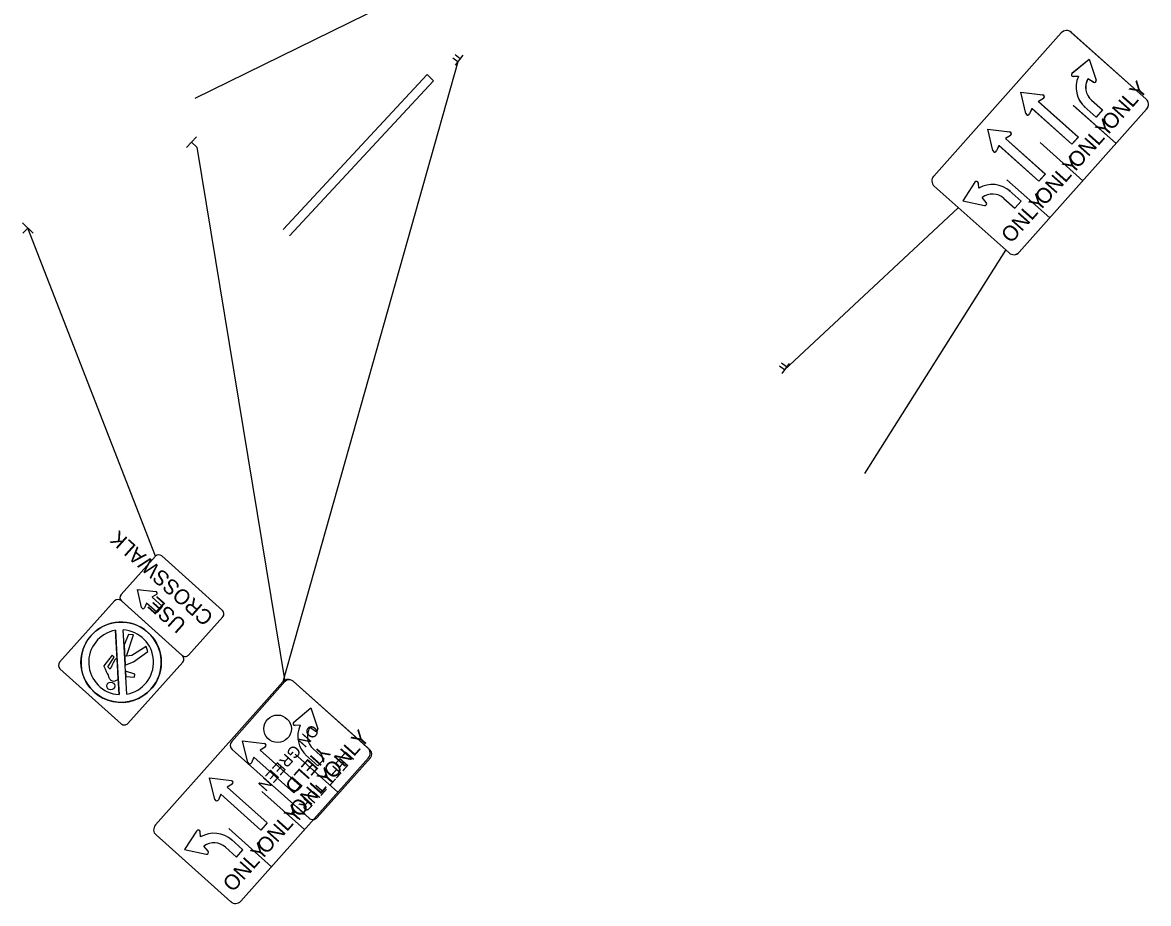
# Model space of a CAD drawing. Extents: x 1472333 to 1475205, y 385587 to 386650.
# Drawn here: x 1473153.5 to 1473399.5, y 385586.8 to 385779.2 of the extents above; entities that cross this region are included whole.
import ezdxf

# ---------------------------------------------------------------- set-up
doc = ezdxf.new("R2010")
doc.units = 0
for name, color, linetype in [('_CIVIL_CONSTRUCTION', 7, 'Continuous'), ('RS_Raster1', 7, 'Continuous'), ('RW_X_CL', 7, 'Continuous'), ('RW_X_CL_500_Cardinal_Points', 7, 'Continuous')]:
    doc.layers.add(name, color=color, linetype=linetype)

msp = doc.modelspace()

# ---------------------------------------------------------------- linework, layer by layer
at = {"layer": '_CIVIL_CONSTRUCTION'}
for p, q in [((1473189.27, 385751.9), (1473191.48, 385754.21)), ((1473190.38, 385753.06), (1473191.53, 385751.95)), ((1473153.47, 385735.4), (1473155.78, 385733.19)), ((1473154.62, 385734.29), (1473153.52, 385733.14)), ((1473182.49, 385662.62), (1473154.62, 385734.29)), ((1473179.47, 385651.44), (1473178.56, 385655.39)), ((1473178.56, 385655.39), (1473182.58, 385654.91)), ((1473181.08, 385653.12), (1473181.08, 385653.12)), ((1473182.72, 385654.27), (1473181.75, 385653.7)), ((1473180.58, 385652.39), (1473180.11, 385651.37)), ((1473180.59, 385652.39), (1473180.58, 385652.39)), ((1473182.88, 385650.33), (1473180.59, 385652.39)), ((1473184.05, 385651.64), (1473182.88, 385650.33)), ((1473174.55, 385632.4), (1473173.8, 385646.46)), ((1473176.62, 385645.55), (1473175.65, 385643.27)), ((1473176.62, 385645.55), (1473175.65, 385643.27)), ((1473175.65, 385643.27), (1473175.88, 385638.91)), ((1473176.18, 385640.78), (1473177.73, 385645.45)), ((1473176.18, 385640.78), (1473177.73, 385645.45)), ((1473177.73, 385645.45), (1473176.62, 385645.55)), ((1473177.73, 385645.45), (1473176.62, 385645.55)), ((1473173.07, 385641.04), (1473171.24, 385638.66)), ((1473173.07, 385641.04), (1473171.24, 385638.66)), ((1473173.51, 385640.58), (1473173.07, 385641.04)), ((1473173.51, 385640.58), (1473173.07, 385641.04)), ((1473177.32, 385640.97), (1473176.18, 385640.78)), ((1473177.32, 385640.97), (1473176.18, 385640.78)), ((1473180.45, 385642.9), (1473177.32, 385640.97)), ((1473180.45, 385642.9), (1473177.32, 385640.97)), ((1473177.74, 385639.58), (1473180.88, 385641.83)), ((1473177.74, 385639.58), (1473180.88, 385641.83)), ((1473180.88, 385641.83), (1473180.45, 385642.9)), ((1473180.88, 385641.83), (1473180.45, 385642.9)), ((1473171.24, 385638.66), (1473171.25, 385638.65)), ((1473171.24, 385638.66), (1473171.25, 385638.65)), ((1473172.08, 385638.44), (1473173.51, 385640.58)), ((1473172.08, 385638.44), (1473173.51, 385640.58)), ((1473172.61, 385637.93), (1473172.08, 385638.44)), ((1473172.61, 385637.93), (1473172.08, 385638.44)), ((1473174.36, 385635.86), (1473174.12, 385640.4)), ((1473175.88, 385638.91), (1473175.89, 385638.82)), ((1473175.89, 385638.82), (1473176.43, 385639.02)), ((1473175.89, 385638.82), (1473176.43, 385639.02)), ((1473176.43, 385639.02), (1473177.74, 385639.58)), ((1473176.43, 385639.02), (1473177.74, 385639.58)), ((1473174.37, 385635.71), (1473174.36, 385635.86)), ((1473178.03, 385636.89), (1473175.96, 385637.53)), ((1473178.03, 385636.89), (1473175.96, 385637.53)), ((1473175.96, 385637.53), (1473175.97, 385637.29)), ((1473176.02, 385636.36), (1473177.94, 385636.19)), ((1473176.02, 385636.36), (1473177.94, 385636.19)), ((1473177.94, 385636.19), (1473178.03, 385636.89)), ((1473177.94, 385636.19), (1473178.03, 385636.89))]:
    msp.add_line(p, q, dxfattribs=at)
for points in [[(1473182.49, 385662.62), (1473175, 385654.27)], [(1473197.14, 385650.79), (1473183.89, 385662.69)], [(1473181.76, 385653.69), (1473184.05, 385651.64)], [(1473173.59, 385652.86), (1473161.57, 385639.47)], [(1473188.4, 385640.91), (1473175, 385652.94)], [(1473175.07, 385652.88), (1473188.33, 385640.98)], [(1473189.72, 385641.05), (1473197.21, 385649.4)], [(1473173.79, 385646.46), (1473174.09, 385640.88), (1473174.09, 385640.88), (1473174.09, 385640.88), (1473174.36, 385635.86), (1473174.36, 385635.86)], [(1473175.97, 385637.29), (1473175.88, 385638.91), (1473175.6, 385644.14), (1473175.47, 385646.55)], [(1473176.45, 385626.11), (1473188.47, 385639.5)], [(1473161.64, 385638.06), (1473175.03, 385626.03)], [(1473174.36, 385635.86), (1473174.55, 385632.4)], [(1473174.36, 385635.86), (1473174.36, 385635.86)], [(1473176.23, 385632.49), (1473176.03, 385636.31), (1473175.96, 385637.29), (1473175.97, 385637.29)], [(1473175.97, 385637.29), (1473176.02, 385636.36), (1473176.02, 385636.36)]]:
    msp.add_lwpolyline(points, dxfattribs=at)
for centre, radius in [((1473175.01, 385639.47), 8.77), ((1473172.74, 385634.29), 0.864)]:
    msp.add_circle(centre, radius, dxfattribs=at)
for centre, radius, start, end in [((1473183.23, 385661.95), 0.989, 48.0785, 138.0785), ((1473174.34, 385652.19), 1, 48.0785, 138.0785), ((1473175.74, 385653.61), 0.989, 138.0785, 228.0785), ((1473182.54, 385654.57), 0.342, 300.4407, 83.1578), ((1473179.8, 385651.51), 0.342, 192.9993, 335.7163), ((1473196.48, 385650.06), 0.989, 318.0785, 48.0785), ((1473175.01, 385639.47), 8.77, 318.0785, 138.0785), ((1473175.01, 385639.47), 7.09, 99.8976, 266.2499), ((1473175.01, 385639.47), 7.09, 99.8976, 266.2499), ((1473175.01, 385639.47), 7.09, 279.9265, 86.3265), ((1473175.01, 385639.47), 7.09, 279.9265, 86.3265), ((1473175.01, 385639.47), 8.77, 138.0785, 318.0785), ((1473188.99, 385641.71), 0.989, 228.0785, 318.0785), ((1473187.73, 385640.17), 1, 318.0785, 48.0785), ((1473162.31, 385638.8), 1, 138.0785, 228.0785), ((1473174.09, 385637.37), 1.54, 280.1537, 280.2069), ((1473175.7, 385626.78), 1, 228.0785, 318.0785)]:
    msp.add_arc(centre, radius, start, end, dxfattribs=at)
for points in [[(1473171.25, 385638.65), (1473171.65, 385637.77), (1473172.26, 385636.37), (1473172.48, 385635.86), (1473172.58, 385635.72), (1473172.71, 385635.61), (1473173.01, 385635.34), (1473173.7, 385635.36), (1473174.11, 385635.58), (1473174.37, 385635.71)], [(1473171.25, 385638.65), (1473171.65, 385637.77), (1473172.26, 385636.37), (1473172.48, 385635.86), (1473172.58, 385635.72), (1473172.71, 385635.61), (1473173.01, 385635.34), (1473173.7, 385635.36), (1473174.11, 385635.58), (1473174.37, 385635.71)], [(1473174.12, 385640.4), (1473174.05, 385640.38), (1473173.86, 385640.26), (1473173.58, 385639.9), (1473173.37, 385639.54), (1473173.03, 385638.87), (1473172.81, 385638.39), (1473172.61, 385637.93)], [(1473174.12, 385640.4), (1473174.05, 385640.38), (1473173.86, 385640.26), (1473173.58, 385639.9), (1473173.37, 385639.54), (1473173.03, 385638.87), (1473172.81, 385638.39), (1473172.61, 385637.93)]]:
    msp.add_open_spline(points, degree=3, dxfattribs=at)
at = {"layer": 'RS_Raster1'}
for p, q in [((1473241.84, 385767.84), (1473210.38, 385733.99)), ((1473211.81, 385732.59), (1473243.28, 385766.46)), ((1473243.28, 385766.46), (1473241.84, 385767.84))]:
    msp.add_line(p, q, dxfattribs=at)
at = {"layer": 'RW_X_CL'}
for p, q in [((1473382.75, 385768.1), (1473386.47, 385771.19)), ((1473386.47, 385771.19), (1473388.02, 385766.61)), ((1473384.14, 385767.39), (1473383.03, 385767.36)), ((1473387.4, 385766.13), (1473386.23, 385766.89)), ((1473371.54, 385763.98), (1473376.34, 385763.38)), ((1473372.69, 385759.29), (1473371.54, 385763.98)), ((1473376.5, 385762.61), (1473375.39, 385761.94)), ((1473375.39, 385761.94), (1473384.13, 385754.16)), ((1473386.98, 385762.22), (1473389.4, 385760.07)), ((1473374.01, 385760.39), (1473373.48, 385759.22)), ((1473382.74, 385752.6), (1473374.01, 385760.39)), ((1473392.37, 385752.75), (1473383.03, 385761.07)), ((1473388.01, 385758.52), (1473385.4, 385760.84)), ((1473385.4, 385760.84), (1473385.59, 385760.66)), ((1473389.4, 385760.07), (1473388.01, 385758.52)), ((1473364.33, 385755.89), (1473369.13, 385755.29)), ((1473365.49, 385751.2), (1473364.33, 385755.89)), ((1473369.29, 385754.52), (1473368.19, 385753.86)), ((1473368.19, 385753.86), (1473376.92, 385746.07)), ((1473384.13, 385754.16), (1473382.74, 385752.6)), ((1473366.8, 385752.3), (1473366.27, 385751.13)), ((1473375.54, 385744.52), (1473366.8, 385752.3)), ((1473385.12, 385744.63), (1473375.79, 385752.94)), ((1473361.54, 385744.29), (1473358.89, 385740.24)), ((1473362.4, 385742.99), (1473362.3, 385744.1)), ((1473377.88, 385736.5), (1473368.55, 385744.81)), ((1473376.92, 385746.07), (1473375.54, 385744.52)), ((1473371.66, 385740.16), (1473369.04, 385742.49)), ((1473369.04, 385742.49), (1473369.25, 385742.32)), ((1473358.89, 385740.24), (1473363.62, 385739.22)), ((1473364.02, 385739.89), (1473363.13, 385740.97)), ((1473367.86, 385740.76), (1473370.27, 385738.61)), ((1473370.27, 385738.61), (1473371.66, 385740.16)), ((1473337.46, 385680.68), (1473368.29, 385729.49))]:
    msp.add_line(p, q, dxfattribs=at)
for points in [[(1473380.39, 385776.89), (1473352.53, 385745.63)], [(1473398.92, 385762.46), (1473382.59, 385777.02)], [(1473371.19, 385728.99), (1473399.05, 385760.26)], [(1473352.66, 385743.42), (1473368.99, 385728.87)]]:
    msp.add_lwpolyline(points, dxfattribs=at)
for centre, radius, start, end in [((1473381.55, 385775.85), 1.56, 48.2955, 138.2955), ((1473383.02, 385767.78), 0.417, 129.7558, 271.6339), ((1473389.48, 385765.02), 5.84, 156.0635, 228.2955), ((1473389.48, 385765.02), 3.75, 150.0723, 228.2955), ((1473387.63, 385766.48), 0.417, 236.9102, 18.7883), ((1473376.29, 385762.96), 0.417, 300.9337, 82.8118), ((1473397.89, 385761.3), 1.56, 318.2955, 48.2955), ((1473373.1, 385759.39), 0.417, 193.7793, 335.6574), ((1473369.08, 385754.88), 0.417, 300.9337, 82.8118), ((1473365.89, 385751.3), 0.417, 193.7793, 335.6574), ((1473353.69, 385744.59), 1.56, 138.2955, 228.2955), ((1473361.88, 385744.06), 0.417, 4.9572, 146.8353), ((1473365.36, 385737.96), 5.84, 48.2955, 120.5275), ((1473365.36, 385737.96), 3.75, 48.2955, 126.5188), ((1473363.7, 385739.63), 0.417, 257.8028, 39.6809), ((1473370.03, 385730.03), 1.56, 228.2955, 318.2955)]:
    msp.add_arc(centre, radius, start, end, dxfattribs=at)
at = {"layer": 'RW_X_CL_500_Cardinal_Points'}
for p, q in [((1473191.19, 385762.67), (1473265.45, 385799.11)), ((1473248.57, 385770.61), (1473247.48, 385771.42)), ((1473249.06, 385771.26), (1473247.97, 385772.08)), ((1473249.63, 385772.03), (1473248, 385769.85)), ((1473382.77, 385768.09), (1473386.48, 385771.18)), ((1473386.48, 385771.18), (1473388.04, 385766.6)), ((1473248.57, 385770.61), (1473210.37, 385635.21)), ((1473248.81, 385770.94), (1473248.81, 385770.94)), ((1473248.81, 385770.94), (1473248.81, 385770.94)), ((1473384.16, 385767.39), (1473383.04, 385767.35)), ((1473387.42, 385766.12), (1473386.24, 385766.89)), ((1473371.56, 385763.98), (1473376.35, 385763.38)), ((1473372.7, 385759.29), (1473371.56, 385763.98)), ((1473376.51, 385762.61), (1473375.41, 385761.94)), ((1473375.41, 385761.94), (1473384.14, 385754.16)), ((1473387, 385762.22), (1473389.41, 385760.06)), ((1473374.02, 385760.39), (1473373.49, 385759.21)), ((1473382.75, 385752.6), (1473374.02, 385760.39)), ((1473392.37, 385752.75), (1473383.05, 385761.07)), ((1473388.02, 385758.51), (1473385.41, 385760.84)), ((1473385.41, 385760.84), (1473385.61, 385760.66)), ((1473389.41, 385760.06), (1473388.02, 385758.51)), ((1473364.34, 385755.9), (1473369.14, 385755.29)), ((1473365.49, 385751.2), (1473364.34, 385755.9)), ((1473369.3, 385754.52), (1473368.2, 385753.86)), ((1473368.2, 385753.86), (1473376.93, 385746.07)), ((1473384.14, 385754.16), (1473382.75, 385752.6)), ((1473191.52, 385751.96), (1473210.81, 385635.24)), ((1473366.81, 385752.3), (1473366.28, 385751.13)), ((1473375.54, 385744.52), (1473366.81, 385752.3)), ((1473385.13, 385744.62), (1473375.8, 385752.94)), ((1473361.54, 385744.29), (1473358.9, 385740.25)), ((1473362.4, 385742.99), (1473362.31, 385744.1)), ((1473377.88, 385736.5), (1473368.55, 385744.81)), ((1473376.93, 385746.07), (1473375.54, 385744.52)), ((1473371.66, 385740.16), (1473369.05, 385742.49)), ((1473369.05, 385742.49), (1473369.25, 385742.32)), ((1473358.9, 385740.25), (1473363.62, 385739.22)), ((1473364.03, 385739.9), (1473363.13, 385740.97)), ((1473367.86, 385740.76), (1473370.27, 385738.61)), ((1473370.27, 385738.61), (1473371.66, 385740.16)), ((1473319.91, 385703.33), (1473357.91, 385738.74)), ((1473320.4, 385703.98), (1473319.31, 385704.79)), ((1473320.97, 385704.74), (1473319.34, 385702.56)), ((1473319.91, 385703.33), (1473318.82, 385704.14)), ((1473320.16, 385703.65), (1473320.16, 385703.65)), ((1473320.16, 385703.65), (1473320.16, 385703.65)), ((1473212.73, 385626.42), (1473216.45, 385629.51)), ((1473216.45, 385629.51), (1473218.01, 385624.93)), ((1473214.12, 385625.71), (1473213.01, 385625.68)), ((1473217.38, 385624.45), (1473216.21, 385625.21)), ((1473201.52, 385622.31), (1473206.32, 385621.7)), ((1473202.67, 385617.61), (1473201.52, 385622.31)), ((1473203.99, 385618.71), (1473203.46, 385617.54)), ((1473212.72, 385610.93), (1473203.99, 385618.71)), ((1473206.48, 385620.93), (1473205.37, 385620.27)), ((1473205.37, 385620.27), (1473214.11, 385612.48)), ((1473222.34, 385611.07), (1473213.01, 385619.39)), ((1473217.99, 385616.83), (1473215.38, 385619.16)), ((1473215.38, 385619.16), (1473215.57, 385618.98)), ((1473216.96, 385620.54), (1473219.38, 385618.39)), ((1473219.38, 385618.39), (1473217.99, 385616.83)), ((1473194.31, 385614.22), (1473199.11, 385613.62)), ((1473195.46, 385609.53), (1473194.31, 385614.22)), ((1473199.27, 385612.85), (1473198.16, 385612.18)), ((1473198.16, 385612.18), (1473206.9, 385604.4)), ((1473215.09, 385602.95), (1473205.77, 385611.27)), ((1473214.11, 385612.48), (1473212.72, 385610.93)), ((1473196.78, 385610.63), (1473196.25, 385609.45)), ((1473205.51, 385602.84), (1473196.78, 385610.63)), ((1473206.9, 385604.4), (1473205.51, 385602.84)), ((1473191.51, 385602.62), (1473188.86, 385598.57)), ((1473192.37, 385601.32), (1473192.27, 385602.42)), ((1473207.85, 385594.82), (1473198.52, 385603.14)), ((1473194, 385598.22), (1473193.1, 385599.3)), ((1473197.83, 385599.08), (1473200.24, 385596.93)), ((1473201.63, 385598.49), (1473199.02, 385600.82)), ((1473199.02, 385600.82), (1473199.22, 385600.64)), ((1473188.86, 385598.57), (1473193.59, 385597.55)), ((1473200.24, 385596.93), (1473201.63, 385598.49))]:
    msp.add_line(p, q, dxfattribs=at)
for points in [[(1473380.41, 385776.89), (1473352.53, 385745.63)], [(1473398.94, 385762.45), (1473382.61, 385777.01)], [(1473371.19, 385728.99), (1473399.06, 385760.25)], [(1473352.66, 385743.43), (1473368.99, 385728.87)], [(1473210.37, 385635.21), (1473182.5, 385603.96)], [(1473199.17, 385622.18), (1473210.81, 385635.24)], [(1473228.9, 385620.78), (1473212.58, 385635.34)], [(1473212.58, 385635.34), (1473229.37, 385620.36)], [(1473216.06, 385605.44), (1473199.27, 385620.41)], [(1473201.16, 385587.32), (1473229.03, 385618.57)], [(1473229.47, 385618.6), (1473217.82, 385605.54)], [(1473182.63, 385601.75), (1473198.95, 385587.19)]]:
    msp.add_lwpolyline(points, dxfattribs=at)
msp.add_circle((1473209.2, 385624.95), 3, dxfattribs=at)
for centre, radius, start, end in [((1473381.57, 385775.85), 1.56, 48.2737, 138.2737), ((1473383.03, 385767.77), 0.417, 129.734, 271.6121), ((1473389.49, 385765.01), 5.84, 156.0417, 228.2737), ((1473389.49, 385765.01), 3.75, 150.0505, 228.2737), ((1473387.64, 385766.47), 0.417, 236.8884, 18.7665), ((1473376.3, 385762.96), 0.417, 300.9119, 82.79), ((1473397.9, 385761.29), 1.56, 318.2737, 48.2737), ((1473373.11, 385759.39), 0.417, 193.7575, 335.6356), ((1473369.09, 385754.88), 0.417, 300.9119, 82.79), ((1473365.9, 385751.3), 0.417, 193.7575, 335.6356), ((1473353.7, 385744.59), 1.56, 138.2737, 228.2737), ((1473361.89, 385744.06), 0.417, 4.9354, 146.8135), ((1473365.37, 385737.96), 5.84, 48.2737, 120.5057), ((1473365.37, 385737.96), 3.75, 48.2737, 126.497), ((1473363.71, 385739.63), 0.417, 257.781, 39.6591), ((1473370.03, 385730.03), 1.56, 228.2737, 318.2737), ((1473211.54, 385634.17), 1.56, 48.2737, 138.2737), ((1473211.75, 385634.41), 1.25, 48.2737, 138.2737), ((1473213, 385626.1), 0.417, 129.734, 271.6121), ((1473219.46, 385623.34), 5.84, 156.0417, 228.2737), ((1473219.46, 385623.34), 3.75, 150.0505, 228.2737), ((1473217.61, 385624.8), 0.417, 236.8884, 18.7665), ((1473200.1, 385621.34), 1.25, 138.2737, 228.2737), ((1473206.27, 385621.29), 0.417, 300.9119, 82.79), ((1473227.86, 385619.61), 1.56, 318.2737, 48.2737), ((1473228.54, 385619.43), 1.25, 318.2737, 48.2737), ((1473203.08, 385617.71), 0.417, 193.7575, 335.6356), ((1473199.06, 385613.2), 0.417, 300.9119, 82.79), ((1473195.87, 385609.63), 0.417, 193.7575, 335.6356), ((1473183.67, 385602.92), 1.56, 138.2737, 228.2737), ((1473216.89, 385606.37), 1.25, 228.2737, 318.2737), ((1473191.86, 385602.39), 0.417, 4.9354, 146.8135), ((1473195.33, 385596.29), 5.84, 48.2737, 120.5057), ((1473195.33, 385596.29), 3.75, 48.2737, 126.497), ((1473193.67, 385597.96), 0.417, 257.781, 39.6591), ((1473199.99, 385588.36), 1.56, 228.2737, 318.2737)]:
    msp.add_arc(centre, radius, start, end, dxfattribs=at)

# ---------------------------------------------------------------- texts
at = {"layer": '_CIVIL_CONSTRUCTION'}
for s, p in [('CROSSWALK', (1473195.41, 385649.6)), ('USE', (1473189.49, 385648))]:
    msp.add_text(s, height=3.296, rotation=138.0785, dxfattribs=at).set_placement(p)
at = {"layer": 'RW_X_CL'}
for p in [(1473391.4, 385755.43), (1473383.99, 385747.12), (1473376.78, 385739.03), (1473369.44, 385730.79)]:
    msp.add_text('ONLY', height=3.333, rotation=48.2955, dxfattribs=at).set_placement(p)
at = {"layer": 'RW_X_CL_500_Cardinal_Points'}
for s, height, rotation, p in [('ONLY', 3.333, 48.2737, (1473391.41, 385755.43)), ('ONLY', 3.333, 48.2737, (1473384, 385747.11)), ('ONLY', 3.333, 48.2737, (1473376.79, 385739.02)), ('ONLY', 3.333, 48.2737, (1473369.44, 385730.79)), ('ON GREEN', 2.503, 228.2737, (1473216.63, 385626.09)), ('ONLY', 3.333, 48.2737, (1473221.38, 385613.75)), ('YIELD', 3.128, 228.2737, (1473218.62, 385621.59)), ('LEFT TURN', 2.503, 228.2737, (1473224.24, 385620.21)), ('ONLY', 3.333, 48.2737, (1473213.97, 385605.44)), ('ONLY', 3.333, 48.2737, (1473206.75, 385597.35)), ('ONLY', 3.333, 48.2737, (1473199.41, 385589.11))]:
    msp.add_text(s, height=height, rotation=rotation, dxfattribs=at).set_placement(p)

doc.saveas('drawing.dxf')
